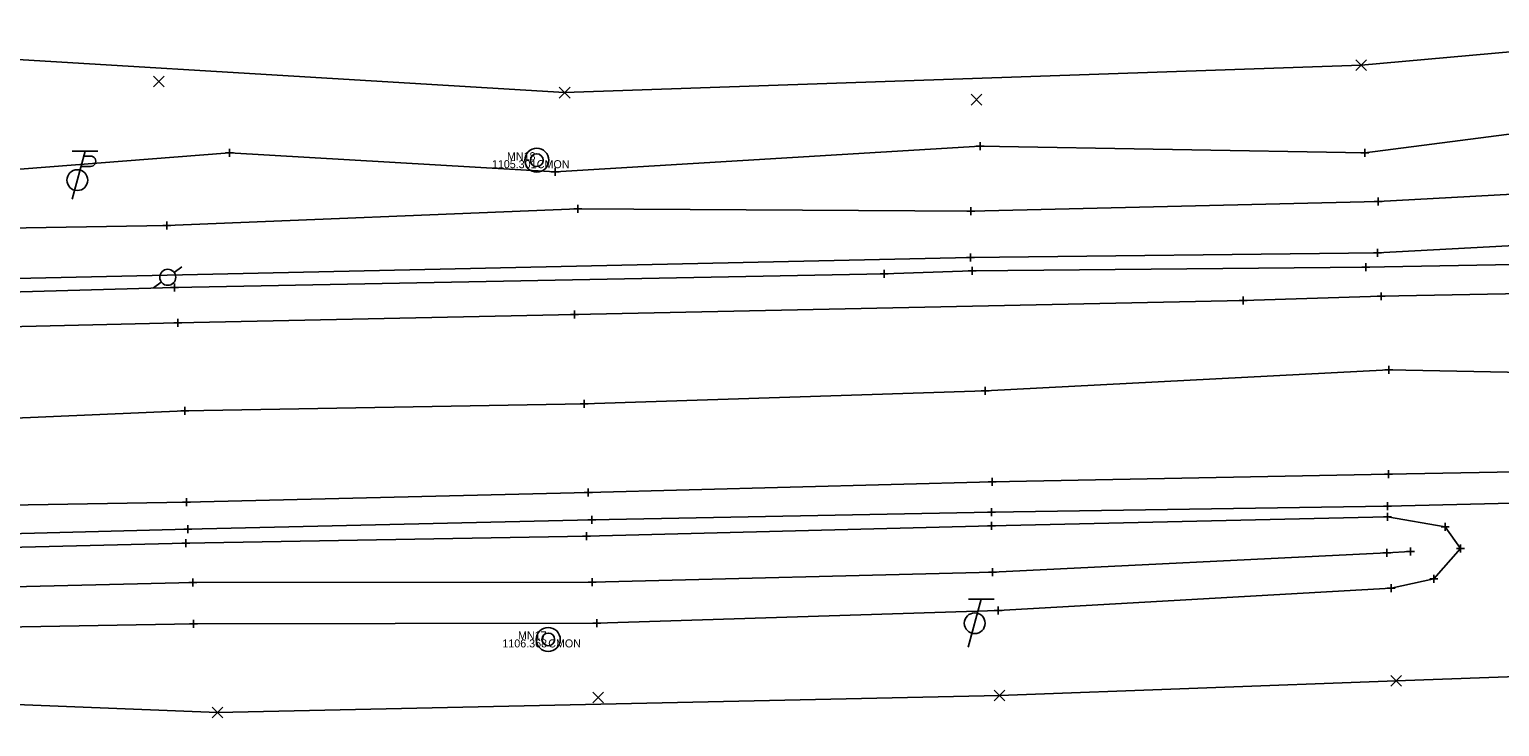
# Model space of a CAD drawing. Extents: x 2402028 to 2407435, y 498611 to 499105.
# Drawn here: x 2402470.5 to 2402654.2, y 498615.1 to 498702.4 of the extents above; entities that cross this region are included whole.
import ezdxf

# ---------------------------------------------------------------- set-up
doc = ezdxf.new("R2010")
doc.units = 0
for name, color, linetype in [('_CIVIL_CONSTRUCTION', 7, 'Continuous'), ('DR_X_Ditch', 7, 'Continuous'), ('PV_X_COP', 7, 'Continuous'), ('PV_X_EOP', 7, 'Continuous'), ('PV_X_Shoulder', 7, 'Continuous'), ('RW_X_CL', 7, 'Continuous'), ('RW_X_CL_1000_Distances', 7, 'Continuous'), ('RW_X_CL_100_Bearings', 7, 'Continuous'), ('RW_X_CL_100_Cardinal_Points', 7, 'Continuous'), ('RW_X_CL_100_Stations', 7, 'Continuous'), ('RW_X_CL_500_Bearings', 7, 'Continuous'), ('RW_X_CL_500_Cardinal_Points', 7, 'Continuous'), ('RW_X_CL_500_Stations', 7, 'Continuous'), ('SV_X_Break_Lines', 7, 'Continuous'), ('SV_X_Terrain_Boundary', 7, 'Continuous')]:
    doc.layers.add(name, color=color, linetype=linetype)

msp = doc.modelspace()

# ---------------------------------------------------------------- linework, layer by layer
at = {"layer": 'DR_X_Ditch'}
for points in [[(2402290.75, 498672.96), (2402338.21, 498675.68), (2402389.11, 498675.91), (2402437.36, 498676.99), (2402487.67, 498677.83), (2402539.05, 498679.9), (2402588.14, 498679.64), (2402639.05, 498680.84), (2402688.69, 498683.54), (2402739.78, 498686.18), (2402783.2, 498688.14)], [(2402643.1, 498637.06), (2402640.15, 498636.9), (2402590.87, 498634.48), (2402540.83, 498633.21), (2402490.91, 498633.16), (2402440.6, 498631.95), (2402391.58, 498630.09), (2402340.2, 498628.99), (2402290.78, 498627.25)]]:
    msp.add_lwpolyline(points, dxfattribs=at)
at = {"layer": 'PV_X_COP'}
msp.add_lwpolyline([(2402290.78, 498650.6), (2402340.95, 498651.54), (2402390.57, 498652.34), (2402439.7, 498652.49), (2402489.93, 498654.64), (2402539.81, 498655.53), (2402589.95, 498657.15), (2402640.38, 498659.77), (2402689.17, 498658.83), (2402739.11, 498659.65), (2402789.43, 498660.95), (2402839.82, 498661.75), (2402889.36, 498663.57), (2402939.81, 498664.58), (2402990.03, 498665.92), (2403038.83, 498667.68), (2403088.96, 498668.97), (2403139.3, 498669.99), (2403188.98, 498670.93), (2403236.78, 498672.43), (2403288.95, 498673.92), (2403339.4, 498675.07), (2403388.6, 498676.54)], dxfattribs=at)
at = {"layer": 'PV_X_EOP'}
for points in [[(2402289.63, 498661.52), (2402339.86, 498662.34), (2402390.35, 498663.57), (2402439.38, 498664.47), (2402489.03, 498665.67), (2402538.63, 498666.7), (2402622.2, 498668.45), (2402639.44, 498668.97), (2402688.21, 498669.91), (2402738.3, 498670.77), (2402784.26, 498671.54), (2402839.07, 498673.4), (2402887.81, 498674.54), (2402939.07, 498675.44), (2402989.96, 498676.81), (2403039.49, 498677.82), (2403088.59, 498679.54), (2403138.58, 498681), (2403188.48, 498682.36), (2403236.31, 498683.8), (2403287.8, 498685.14), (2403338.61, 498686.54), (2403387.34, 498688.53)], [(2402290.91, 498639.29), (2402341.07, 498640.3), (2402390.61, 498641.23), (2402440.65, 498642.38), (2402490.15, 498643.23), (2402540.35, 498644.45), (2402590.8, 498645.77), (2402640.33, 498646.73), (2402690.18, 498647.64), (2402739.92, 498648.63), (2402790, 498649.56), (2402840.05, 498650.65), (2402889.89, 498651.78), (2402940.17, 498653.2), (2402989.78, 498654.87), (2403039.63, 498656.02), (2403089.54, 498657.39), (2403140.04, 498658.56), (2403189.82, 498659.81), (2403238.57, 498661.04), (2403289.76, 498662.62), (2403340.13, 498663.91), (2403389.07, 498665.43)]]:
    msp.add_lwpolyline(points, dxfattribs=at)
at = {"layer": 'PV_X_Shoulder'}
for p, q in [((2402637.5, 498672.61), (2402688.04, 498673.54)), ((2402488.62, 498670.06), (2402577.32, 498671.8)), ((2402577.32, 498671.8), (2402588.32, 498672.15)), ((2402588.32, 498672.15), (2402637.5, 498672.61)), ((2402437.96, 498668.64), (2402488.62, 498670.06))]:
    msp.add_line(p, q, dxfattribs=at)
msp.add_lwpolyline([(2402291.13, 498635.58), (2402341.06, 498636.96), (2402390.62, 498637.69), (2402440.73, 498638.55), (2402490.3, 498639.85), (2402540.78, 498641.01), (2402590.73, 498641.96), (2402640.23, 498642.72), (2402690.38, 498643.95), (2402740.06, 498644.93), (2402790, 498645.7), (2402840.23, 498646.8), (2402889.99, 498648.42), (2402940.22, 498649.59), (2402989.85, 498649.92), (2403040.06, 498650.63), (2403089.93, 498652.73), (2403140.24, 498654.26), (2403189.57, 498655.62), (2403238.67, 498657.76), (2403289.89, 498659.04), (2403340.12, 498659.5), (2403389.1, 498660.69)], dxfattribs=at)
at = {"layer": 'RW_X_CL'}
for p, q in [((2402489.55, 498672.67), (2402488.59, 498671.95)), ((2402486.98, 498670.75), (2402486.02, 498670.03))]:
    msp.add_line(p, q, dxfattribs=at)
msp.add_circle((2402487.79, 498671.35), 1, dxfattribs=at)
at = {"layer": 'RW_X_CL_1000_Distances'}
for p, q in [((2402589.45, 498631.07), (2402587.84, 498625.07)), ((2402591.05, 498631.07), (2402587.85, 498631.07))]:
    msp.add_line(p, q, dxfattribs=at)
msp.add_circle((2402588.64, 498628.07), 1.3, dxfattribs=at)
at = {"layer": 'RW_X_CL_100_Stations'}
for centre, radius in [((2402533.91, 498686), 1.5), ((2402533.91, 498686), 0.8), ((2402535.34, 498626.05), 1.5), ((2402535.34, 498626.05), 0.8)]:
    msp.add_circle(centre, radius, dxfattribs=at)
at = {"layer": 'RW_X_CL_500_Bearings'}
for p, q in [((2402589.33, 498688.24), (2402589.33, 498687.24)), ((2402495.01, 498686.91), (2402496.01, 498686.91)), ((2402495.51, 498687.41), (2402495.51, 498686.41)), ((2402495.51, 498686.91), (2402495.51, 498686.91)), ((2402588.83, 498687.74), (2402589.83, 498687.74)), ((2402589.33, 498687.74), (2402589.33, 498687.74)), ((2402636.9, 498686.94), (2402637.9, 498686.94)), ((2402637.4, 498687.44), (2402637.4, 498686.44)), ((2402637.4, 498686.94), (2402637.4, 498686.94)), ((2402535.7, 498684.54), (2402536.7, 498684.54)), ((2402536.2, 498685.04), (2402536.2, 498684.04)), ((2402536.2, 498684.54), (2402536.2, 498684.54)), ((2402539.05, 498680.4), (2402539.05, 498679.4)), ((2402638.55, 498680.84), (2402639.55, 498680.84)), ((2402639.05, 498681.34), (2402639.05, 498680.34)), ((2402639.05, 498680.84), (2402639.05, 498680.84)), ((2402538.55, 498679.9), (2402539.55, 498679.9)), ((2402539.05, 498679.9), (2402539.05, 498679.9)), ((2402587.64, 498679.64), (2402588.64, 498679.64)), ((2402588.14, 498680.14), (2402588.14, 498679.14)), ((2402588.14, 498679.64), (2402588.14, 498679.64)), ((2402487.17, 498677.83), (2402488.17, 498677.83)), ((2402487.67, 498678.33), (2402487.67, 498677.33)), ((2402487.67, 498677.83), (2402487.67, 498677.83)), ((2402638.99, 498674.92), (2402638.99, 498673.92)), ((2402587.61, 498673.81), (2402588.61, 498673.81)), ((2402588.11, 498674.31), (2402588.11, 498673.31)), ((2402588.11, 498673.81), (2402588.11, 498673.81)), ((2402637.5, 498673.11), (2402637.5, 498672.11)), ((2402638.49, 498674.42), (2402639.49, 498674.42)), ((2402638.99, 498674.42), (2402638.99, 498674.42)), ((2402576.82, 498671.8), (2402577.82, 498671.8)), ((2402577.32, 498672.3), (2402577.32, 498671.3)), ((2402577.32, 498671.8), (2402577.32, 498671.8)), ((2402587.82, 498672.15), (2402588.82, 498672.15)), ((2402588.32, 498672.65), (2402588.32, 498671.65)), ((2402588.32, 498672.15), (2402588.32, 498672.15)), ((2402637, 498672.61), (2402638, 498672.61)), ((2402637.5, 498672.61), (2402637.5, 498672.61)), ((2402488.12, 498670.06), (2402489.12, 498670.06)), ((2402488.62, 498670.56), (2402488.62, 498669.56)), ((2402488.62, 498670.06), (2402488.62, 498670.06)), ((2402639.44, 498669.47), (2402639.44, 498668.47)), ((2402621.7, 498668.45), (2402622.7, 498668.45)), ((2402622.2, 498668.95), (2402622.2, 498667.95)), ((2402622.2, 498668.45), (2402622.2, 498668.45)), ((2402638.94, 498668.97), (2402639.94, 498668.97)), ((2402639.44, 498668.97), (2402639.44, 498668.97)), ((2402489.03, 498666.17), (2402489.03, 498665.17)), ((2402538.13, 498666.7), (2402539.13, 498666.7)), ((2402538.63, 498667.2), (2402538.63, 498666.2)), ((2402538.63, 498666.7), (2402538.63, 498666.7)), ((2402488.53, 498665.67), (2402489.53, 498665.67)), ((2402489.03, 498665.67), (2402489.03, 498665.67)), ((2402640.38, 498660.27), (2402640.38, 498659.27)), ((2402639.88, 498659.77), (2402640.88, 498659.77)), ((2402640.38, 498659.77), (2402640.38, 498659.77)), ((2402589.45, 498657.15), (2402590.45, 498657.15)), ((2402589.95, 498657.65), (2402589.95, 498656.65)), ((2402589.95, 498657.15), (2402589.95, 498657.15)), ((2402489.93, 498655.14), (2402489.93, 498654.14)), ((2402539.31, 498655.53), (2402540.31, 498655.53)), ((2402539.81, 498656.03), (2402539.81, 498655.03)), ((2402539.81, 498655.53), (2402539.81, 498655.53)), ((2402489.43, 498654.64), (2402490.43, 498654.64)), ((2402489.93, 498654.64), (2402489.93, 498654.64)), ((2402590.3, 498645.77), (2402591.3, 498645.77)), ((2402590.8, 498646.27), (2402590.8, 498645.27)), ((2402590.8, 498645.77), (2402590.8, 498645.77)), ((2402639.83, 498646.73), (2402640.83, 498646.73)), ((2402640.33, 498647.23), (2402640.33, 498646.23)), ((2402640.33, 498646.73), (2402640.33, 498646.73)), ((2402490.15, 498643.73), (2402490.15, 498642.73)), ((2402539.85, 498644.45), (2402540.85, 498644.45)), ((2402540.35, 498644.95), (2402540.35, 498643.95)), ((2402540.35, 498644.45), (2402540.35, 498644.45)), ((2402489.65, 498643.23), (2402490.65, 498643.23)), ((2402490.15, 498643.23), (2402490.15, 498643.23)), ((2402590.23, 498641.96), (2402591.23, 498641.96)), ((2402590.73, 498642.46), (2402590.73, 498641.46)), ((2402590.73, 498641.96), (2402590.73, 498641.96)), ((2402639.73, 498642.72), (2402640.73, 498642.72)), ((2402640.21, 498641.9), (2402640.21, 498640.9)), ((2402640.23, 498643.22), (2402640.23, 498642.22)), ((2402640.23, 498642.72), (2402640.23, 498642.72)), ((2402490.3, 498640.35), (2402490.3, 498639.35)), ((2402540.28, 498641.01), (2402541.28, 498641.01)), ((2402540.78, 498641.51), (2402540.78, 498640.51)), ((2402540.78, 498641.01), (2402540.78, 498641.01)), ((2402590.25, 498640.26), (2402591.25, 498640.26)), ((2402590.75, 498640.76), (2402590.75, 498639.76)), ((2402590.75, 498640.26), (2402590.75, 498640.26)), ((2402639.71, 498641.4), (2402640.71, 498641.4)), ((2402640.21, 498641.4), (2402640.21, 498641.4)), ((2402646.94, 498640.13), (2402647.94, 498640.13)), ((2402647.44, 498640.63), (2402647.44, 498639.63)), ((2402647.44, 498640.13), (2402647.44, 498640.13)), ((2402489.8, 498639.85), (2402490.8, 498639.85)), ((2402490.04, 498638.58), (2402490.04, 498637.58)), ((2402490.3, 498639.85), (2402490.3, 498639.85)), ((2402539.61, 498638.97), (2402540.61, 498638.97)), ((2402540.11, 498639.47), (2402540.11, 498638.47)), ((2402540.11, 498638.97), (2402540.11, 498638.97)), ((2402489.54, 498638.08), (2402490.54, 498638.08)), ((2402490.04, 498638.08), (2402490.04, 498638.08)), ((2402639.65, 498636.9), (2402640.65, 498636.9)), ((2402640.15, 498637.4), (2402640.15, 498636.4)), ((2402640.15, 498636.9), (2402640.15, 498636.9)), ((2402642.6, 498637.06), (2402643.6, 498637.06)), ((2402643.1, 498637.56), (2402643.1, 498636.56)), ((2402643.1, 498637.06), (2402643.1, 498637.06)), ((2402648.85, 498637.43), (2402649.85, 498637.43)), ((2402649.35, 498637.93), (2402649.35, 498636.93)), ((2402649.35, 498637.43), (2402649.35, 498637.43)), ((2402590.37, 498634.48), (2402591.37, 498634.48)), ((2402590.87, 498634.98), (2402590.87, 498633.98)), ((2402590.87, 498634.48), (2402590.87, 498634.48)), ((2402490.41, 498633.16), (2402491.41, 498633.16)), ((2402490.91, 498633.66), (2402490.91, 498632.66)), ((2402490.91, 498633.16), (2402490.91, 498633.16)), ((2402540.33, 498633.21), (2402541.33, 498633.21)), ((2402540.83, 498633.71), (2402540.83, 498632.71)), ((2402540.83, 498633.21), (2402540.83, 498633.21)), ((2402640.67, 498632.95), (2402640.67, 498631.95)), ((2402645.51, 498633.62), (2402646.51, 498633.62)), ((2402646.01, 498634.12), (2402646.01, 498633.12)), ((2402646.01, 498633.62), (2402646.01, 498633.62)), ((2402640.17, 498632.45), (2402641.17, 498632.45)), ((2402640.67, 498632.45), (2402640.67, 498632.45)), ((2402591.05, 498629.68), (2402592.05, 498629.68)), ((2402591.55, 498630.18), (2402591.55, 498629.18)), ((2402591.55, 498629.68), (2402591.55, 498629.68)), ((2402490.5, 498628), (2402491.5, 498628)), ((2402491, 498628.5), (2402491, 498627.5)), ((2402491, 498628), (2402491, 498628)), ((2402540.92, 498628.09), (2402541.92, 498628.09)), ((2402541.42, 498628.59), (2402541.42, 498627.59)), ((2402541.42, 498628.09), (2402541.42, 498628.09))]:
    msp.add_line(p, q, dxfattribs=at)
at = {"layer": 'RW_X_CL_500_Cardinal_Points'}
for p, q in [((2402479.05, 498687.11), (2402475.85, 498687.11)), ((2402477.45, 498687.11), (2402475.85, 498681.11)), ((2402477.29, 498686.51), (2402478.14, 498686.51)), ((2402476.95, 498685.23), (2402478.14, 498685.23))]:
    msp.add_line(p, q, dxfattribs=at)
msp.add_circle((2402476.49, 498683.51), 1.3, dxfattribs=at)
msp.add_arc((2402478.16, 498685.87), 0.638, 268.8767, 91.1233, dxfattribs=at)
at = {"layer": 'RW_X_CL_500_Stations'}
for p, q in [((2402636.26, 498697.21), (2402637.59, 498698.54)), ((2402636.26, 498698.54), (2402637.59, 498697.21)), ((2402486, 498695.16), (2402487.34, 498696.5)), ((2402486, 498696.5), (2402487.34, 498695.16)), ((2402536.72, 498693.78), (2402538.06, 498695.12)), ((2402536.72, 498695.12), (2402538.06, 498693.78)), ((2402588.19, 498692.9), (2402589.52, 498694.24)), ((2402588.19, 498694.24), (2402589.52, 498692.9)), ((2402640.64, 498620.21), (2402641.97, 498621.54)), ((2402640.64, 498621.54), (2402641.97, 498620.21)), ((2402540.92, 498618.13), (2402542.25, 498619.47)), ((2402540.92, 498619.47), (2402542.25, 498618.13)), ((2402591.07, 498618.37), (2402592.4, 498619.71)), ((2402591.07, 498619.71), (2402592.4, 498618.37)), ((2402493.34, 498616.26), (2402494.67, 498617.59)), ((2402493.34, 498617.59), (2402494.67, 498616.26))]:
    msp.add_line(p, q, dxfattribs=at)
at = {"layer": 'SV_X_Break_Lines'}
for points in [[(2402288.25, 498667.48), (2402339.69, 498668.17), (2402389.86, 498669.48), (2402438.42, 498670.54), (2402588.11, 498673.81), (2402638.99, 498674.42), (2402672.44, 498676.2), (2402688.28, 498675.46), (2402738.27, 498675.88), (2402788.35, 498678.35), (2402793.91, 498678.03), (2402796.15, 498678.69), (2402799.15, 498678), (2402838.74, 498678.94), (2402887.97, 498680.68), (2402923.89, 498681.63), (2402938.31, 498682.59), (2402988.84, 498684.41), (2403028.61, 498685.67), (2403039.38, 498686.37), (2403044.21, 498687.92), (2403044.42, 498694.26), (2403040.83, 498698.9), (2403035.04, 498699.28)], [(2402292.1, 498676.55), (2402340.39, 498678.44), (2402390.48, 498683.5), (2402437.19, 498682.37), (2402495.51, 498686.91), (2402536.2, 498684.54), (2402589.33, 498687.74), (2402637.4, 498686.94), (2402692.15, 498694.03), (2402740.25, 498691.21), (2402794.17, 498690.34)], [(2402290.79, 498633.74), (2402340.74, 498634.03), (2402390.59, 498635.17), (2402440.45, 498636.89), (2402490.04, 498638.08), (2402540.11, 498638.97), (2402590.75, 498640.26), (2402640.21, 498641.4), (2402647.44, 498640.13), (2402649.35, 498637.43), (2402646.01, 498633.62), (2402640.67, 498632.45), (2402591.55, 498629.68), (2402541.42, 498628.09), (2402491, 498628), (2402440.89, 498627.12), (2402390.75, 498624.78), (2402342.08, 498624.54), (2402291.99, 498623.36)]]:
    msp.add_lwpolyline(points, dxfattribs=at)
at = {"layer": 'SV_X_Terrain_Boundary'}
for points in [[(2402686.71, 498702.37), (2402636.92, 498697.87), (2402537.39, 498694.45), (2402439.32, 498700.39), (2402344.8, 498690.53), (2402290.43, 498692.23), (2402292.1, 498676.55), (2402290.75, 498672.96), (2402288.25, 498667.48)], [(2402288.25, 498667.48), (2402289.19, 498666.13), (2402289.63, 498661.52), (2402290.78, 498650.6), (2402290.91, 498639.29), (2402291.13, 498635.58), (2402290.79, 498633.74), (2402290.78, 498627.25), (2402291.99, 498623.36), (2402299.24, 498615.14), (2402383.53, 498615.85), (2402433.13, 498619.34), (2402494, 498616.92), (2402591.74, 498619.04), (2402641.3, 498620.88), (2402692.24, 498622.71)]]:
    msp.add_lwpolyline(points, dxfattribs=at)

# ---------------------------------------------------------------- texts
at = {"layer": '_CIVIL_CONSTRUCTION'}
for s, p in [('MN18', (2402530.18, 498686)), ('MN17', (2402531.56, 498626.05))]:
    msp.add_text(s, height=1, dxfattribs=at).set_placement(p)
at = {"layer": 'RW_X_CL_100_Bearings'}
for s, p in [('1105.301', (2402528.3, 498685)), ('1106.368', (2402529.61, 498625.05))]:
    msp.add_text(s, height=1, dxfattribs=at).set_placement(p)
at = {"layer": 'RW_X_CL_100_Cardinal_Points'}
for p in [(2402533.91, 498685), (2402535.34, 498625.05)]:
    msp.add_text('CMON', height=1, dxfattribs=at).set_placement(p)

doc.saveas('drawing.dxf')
